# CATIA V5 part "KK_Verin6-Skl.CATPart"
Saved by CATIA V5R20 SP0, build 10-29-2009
Part number: Verin6-Skl
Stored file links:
  G:\Khaled_CFAO_2011\ST2M\ST2M_GR1\msallin\Khaled\Version_Finale\KK_Verin6-Skl.CATPart
  C:\Users\Mathieu\Desktop\Think Motion\JOUG-MELEE2.CATProduct
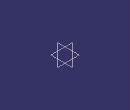
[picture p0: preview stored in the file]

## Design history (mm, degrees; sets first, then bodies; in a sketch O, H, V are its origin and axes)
Set1
  Point1: linked copy from another document
  Point2: linked copy from another document
Body1 (main body)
